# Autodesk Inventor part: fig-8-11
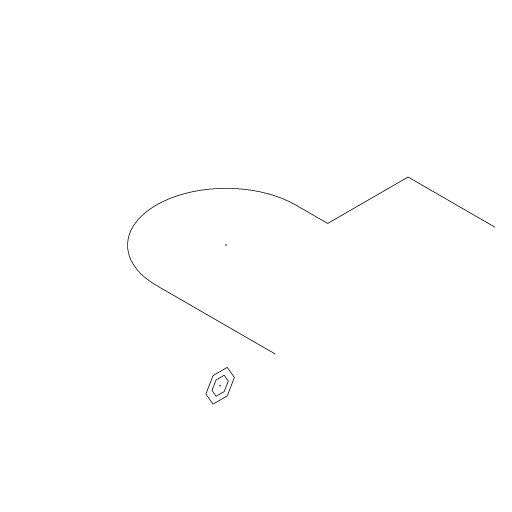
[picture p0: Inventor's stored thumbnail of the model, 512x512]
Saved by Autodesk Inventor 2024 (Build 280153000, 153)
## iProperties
Created: 2004-05
Part Number: fig-8-11
Document SubType Name: Modeling
Designer: CADCIM Technologies
Manufacturer: Standard
Standards Organization: Custom
Density: 1 g/cm^3
Material: Generic
Appearance: Default
Author: CADCIM Technologies
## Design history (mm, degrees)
sketch "Sketch1"
  geometry: L1 (-42.583, 3.219)-(-90.066, 3.219); L2 (-90.066, 58.92)-(-77.282, 58.92); L3 (-77.282, 58.92)-(-77.282, 91.063); L4 (-77.282, 91.063)-(-42.583, 91.063); A1 r 27.851 centre (-90.066, 31.07) between (-90.066, 58.92) and (-90.066, 3.219)
  constraints: 8 end point, 2 parallel, 2 point on circle, 2 tangent, 1 centre point, 1 perpendicular
workplane "Work Plane2"
body "Solid1"
sketch "Sketch2"
  geometry: L1 (16.303, 0)-(19.151, 4.934); L2 (19.151, 4.934)-(24.849, 4.934); L3 (24.849, 4.934)-(27.697, 0); L4 (27.697, 0)-(24.849, -4.934); L5 (24.849, -4.934)-(19.151, -4.934); L6 (19.151, -4.934)-(16.303, 0); L7 (18.744, 0)-(20.372, 2.819); L8 (20.372, 2.819)-(23.628, 2.819); L9 (23.628, 2.819)-(25.256, 0); L10 (25.256, 0)-(23.628, -2.819); L11 (23.628, -2.819)-(20.372, -2.819); L12 (20.372, -2.819)-(18.744, 0); 2 further points
  constraints: 24 end point, 1 coincident, 22 other
